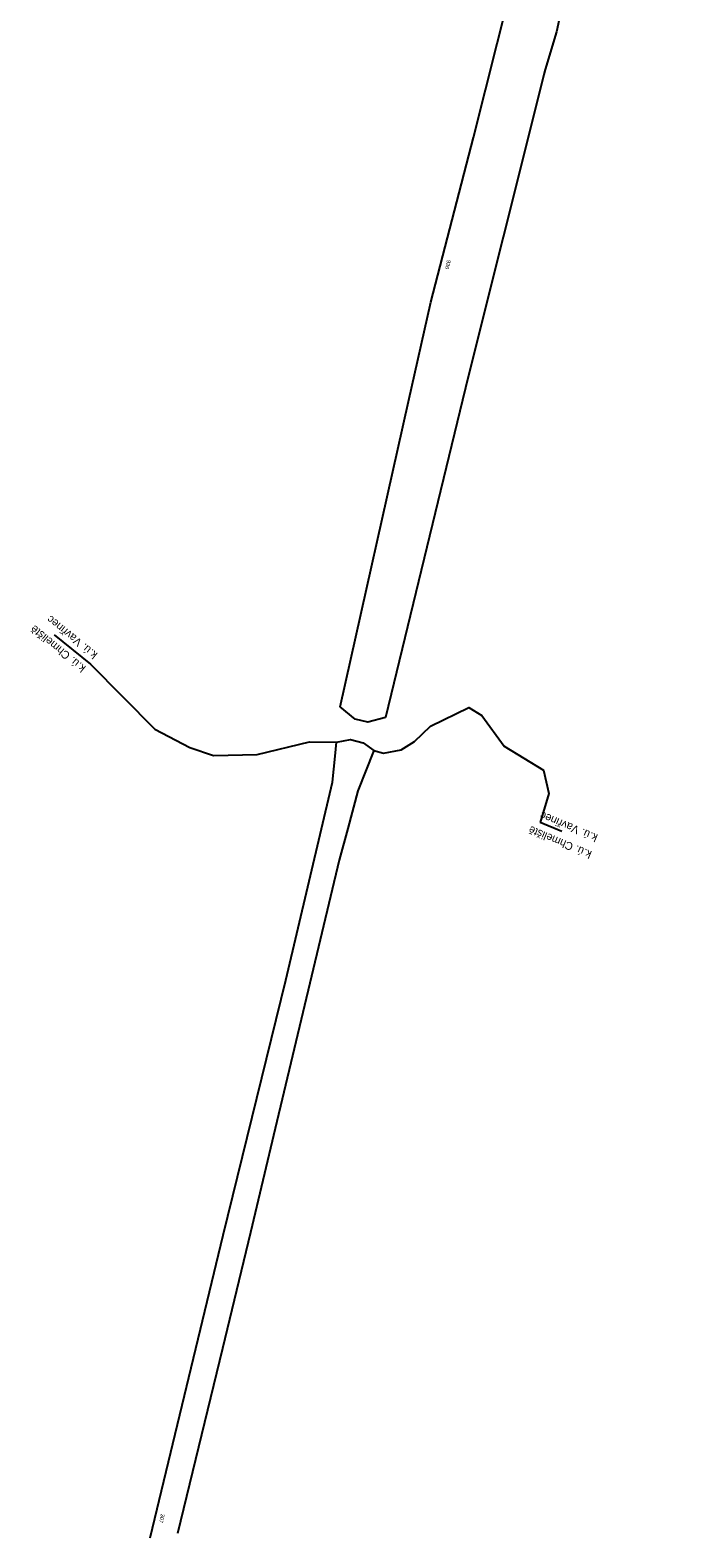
# Model space of a CAD drawing. Extents: x -700390 to -699853, y -1069116 to -1066813.
# Drawn here: x -700390 to -700141, y -1069116 to -1068544 of the extents above; entities that cross this region are included whole.
import ezdxf

# ---------------------------------------------------------------- set-up
doc = ezdxf.new("R2010")
doc.units = 0
for name, color, linetype in [('Vrstva 53', 7, 'Continuous'), ('Vrstva 55', 7, 'Continuous'), ('Vrstva 57', 7, 'Continuous')]:
    doc.layers.add(name, color=color, linetype=linetype)

msp = doc.modelspace()

# ---------------------------------------------------------------- linework, layer by layer
at = {"layer": 'Vrstva 53'}
for points in [[(-700272.12, -1068800.51), (-700246.17, -1068684.7), (-700237.75, -1068646.92), (-700221.56, -1068584.43), (-700207.93, -1068530.57), (-700210.28, -1068524.2), (-700198.49, -1068478.05), (-700194.85, -1068463.81), (-700189.02, -1068437.35), (-700192.53, -1068428.86), (-700193.12, -1068418.31), (-700188.9, -1068405.42), (-700184.91, -1068389.94), (-700176.8, -1068375.11), (-700175.39, -1068368.78), (-700182.31, -1068347.21), (-700181.37, -1068333.01), (-700177.85, -1068321.88), (-700163.08, -1068299.57), (-700161.14, -1068304.49)], [(-700161.14, -1068304.49), (-700153.1, -1068320.98), (-700140.98, -1068348.78), (-700149.35, -1068370.18), (-700158.83, -1068410.48), (-700150.45, -1068415.57), (-700163.64, -1068446.83), (-700165.37, -1068453.9), (-700167.28, -1068461.72), (-700171.14, -1068459.26), (-700178.95, -1068499.23), (-700184.18, -1068520.35), (-700187.39, -1068531.97), (-700190.09, -1068544.45), (-700194.37, -1068558.7), (-700194.83, -1068560.61), (-700197.02, -1068569.35), (-700223.59, -1068675.31), (-700254.95, -1068804.54), (-700261.58, -1068806.34), (-700266.43, -1068805.1), (-700272.12, -1068800.51)], [(-700344.11, -1069115.7), (-700316.48, -1069000.88), (-700292.75, -1068904.2), (-700274.94, -1068829.06), (-700273.97, -1068819.19), (-700273.44, -1068813.82)], [(-700273.44, -1068813.82), (-700268.23, -1068812.87), (-700263.37, -1068814.09), (-700259.29, -1068817.07), (-700265.43, -1068832.3), (-700269.22, -1068846.6), (-700272.41, -1068858.62), (-700296.72, -1068960.45), (-700306.13, -1068999.88), (-700316.68, -1069043.93), (-700333.83, -1069114.03)]]:
    msp.add_lwpolyline(points, dxfattribs=at)
at = {"layer": 'Vrstva 55'}
for points in [[(-700380.55, -1068773.09), (-700366.81, -1068784.27), (-700342.4, -1068808.94), (-700329.05, -1068815.88), (-700320.19, -1068818.93), (-700303.51, -1068818.54), (-700283.74, -1068813.71), (-700273.44, -1068813.82), (-700268.23, -1068812.87), (-700263.37, -1068814.09), (-700259.29, -1068817.07), (-700255.71, -1068818.04), (-700249, -1068816.79), (-700243.87, -1068813.61), (-700237.8, -1068807.86), (-700223.23, -1068800.66), (-700218.32, -1068803.75), (-700209.93, -1068815.43), (-700194.95, -1068824.44), (-700192.97, -1068833.37), (-700196.23, -1068844.31)], [(-700188, -1068847.75), (-700196.23, -1068844.31)]]:
    msp.add_lwpolyline(points, dxfattribs=at)

# ---------------------------------------------------------------- texts
for s, rotation, p in [('k.ú. Vavřinec', 140.8653, (-700363.86, -1068780.25)), ('k.ú. Chmeliště', 140.8653, (-700368.32, -1068785.29)), ('k.ú. Vavřinec', 157.3159, (-700174.13, -1068849.01)), ('k.ú. Chmeliště', 157.3159, (-700176.4, -1068855.34))]:
    msp.add_text(s, height=3, rotation=rotation, dxfattribs=at).set_placement(p)
at = {"layer": 'Vrstva 57'}
for s, rotation, p in [('936', 256.3917, (-700231.55, -1068630.83)), ('307', 256.4264, (-700340.03, -1069106.48))]:
    msp.add_text(s, height=1.5, rotation=rotation, dxfattribs=at).set_placement(p)

doc.saveas('drawing.dxf')
